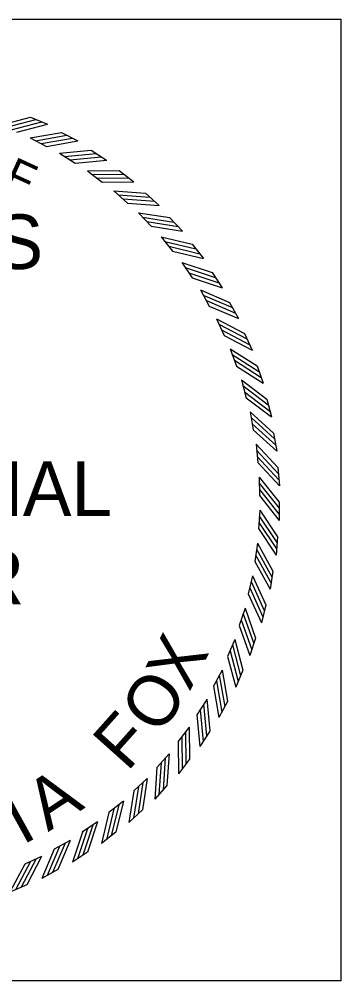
# Model space of a CAD drawing. Extents: x 0 to 1228740, y 0 to 152440.
# Drawn here: x 32.49 to 33.408, y 23.111 to 25.853 of the extents above; entities that cross this region are included whole.
import ezdxf

# ---------------------------------------------------------------- set-up
doc = ezdxf.new("R2010")
doc.units = 0
doc.layers.add('R_No Plot', color=7, linetype='Continuous')
doc.layers.add('STAMP', color=7, linetype='Continuous')

msp = doc.modelspace()

# ---------------------------------------------------------------- linework, layer by layer
at = {"layer": 'R_No Plot'}
msp.add_lwpolyline([(30.6665, 25.8526), (33.4082, 25.8526), (33.4082, 23.1109), (30.6665, 23.1109)], close=True, dxfattribs=at)
at = {"layer": 'STAMP'}
for p, q in [((32.5224, 25.5738), (32.5705, 25.5532)), ((32.6109, 25.53), (32.6572, 25.5055)), ((32.5216, 25.5141), (32.568, 25.4896)), ((32.6052, 25.4706), (32.6494, 25.4423)), ((32.6955, 25.479), (32.7396, 25.4507)), ((32.6849, 25.4203), (32.7266, 25.3884)), ((32.7756, 25.4212), (32.8172, 25.3894)), ((32.7602, 25.3635), (32.7992, 25.3283)), ((32.8506, 25.3569), (32.8895, 25.3218)), ((32.8305, 25.3008), (32.8665, 25.2625)), ((32.9201, 25.2867), (32.956, 25.2485)), ((32.8954, 25.2324), (32.9281, 25.1913)), ((32.9836, 25.211), (33.0161, 25.17)), ((32.9545, 25.1589), (32.9836, 25.1152)), ((33.0406, 25.1304), (33.0696, 25.0868)), ((33.0073, 25.0808), (33.0327, 25.0349)), ((33.0907, 25.0452), (33.1161, 24.9994)), ((33.0534, 24.9986), (33.075, 24.9507)), ((33.1336, 24.9563), (33.1551, 24.9085)), ((33.0927, 24.9129), (33.1102, 24.8634)), ((33.1691, 24.8641), (33.1865, 24.8147)), ((33.1246, 24.8242), (33.138, 24.7734)), ((33.1968, 24.7693), (33.2101, 24.7186)), ((33.1492, 24.7332), (33.1583, 24.6815)), ((33.2165, 24.6725), (33.2256, 24.6209)), ((33.1662, 24.6405), (33.171, 24.5882)), ((33.2283, 24.5744), (33.2331, 24.5222)), ((33.1754, 24.5467), (33.1759, 24.4942)), ((33.2318, 24.4757), (33.2323, 24.4233)), ((33.1769, 24.4524), (33.173, 24.4)), ((33.2273, 24.377), (33.2234, 24.3247)), ((33.1706, 24.3584), (33.1624, 24.3065)), ((33.1565, 24.2651), (33.1441, 24.2141)), ((33.2145, 24.279), (33.2064, 24.2273)), ((33.1938, 24.1825), (33.1814, 24.1316)), ((33.1348, 24.1734), (33.1182, 24.1236)), ((33.1056, 24.0838), (33.0849, 24.0355)), ((33.1651, 24.0879), (33.1485, 24.0382)), ((33.0691, 23.9969), (33.0445, 23.9505)), ((33.1287, 23.9961), (33.1081, 23.9479)), ((33.0255, 23.9133), (32.9972, 23.869)), ((33.0849, 23.9076), (33.0604, 23.8613)), ((32.9752, 23.8336), (32.9433, 23.7918)), ((33.0339, 23.823), (33.0056, 23.7789)), ((32.9184, 23.7583), (32.8832, 23.7193)), ((32.9761, 23.7429), (32.9443, 23.7012)), ((32.8557, 23.6879), (32.8174, 23.652)), ((32.9119, 23.6678), (32.8767, 23.629)), ((32.7873, 23.623), (32.7462, 23.5904)), ((32.8417, 23.5983), (32.8034, 23.5625)), ((32.7138, 23.564), (32.6701, 23.5348)), ((32.766, 23.5349), (32.7249, 23.5023)), ((32.6357, 23.5112), (32.5898, 23.4858)), ((32.6853, 23.4779), (32.6417, 23.4488)), ((32.5535, 23.465), (32.5056, 23.4435)), ((32.6002, 23.4278), (32.5543, 23.4024)), ((32.5112, 23.3848), (32.4634, 23.3634))]:
    msp.add_line(p, q, dxfattribs=at)
for points in [[(32.4346, 25.5506), (32.5223, 25.5738)], [(32.4501, 25.5439), (32.5377, 25.567)], [(32.4669, 25.5371), (32.5546, 25.5602)], [(32.4829, 25.5301), (32.5706, 25.5532)], [(32.5215, 25.5141), (32.6108, 25.53)], [(32.5363, 25.5061), (32.6256, 25.5219)], [(32.5526, 25.4979), (32.6419, 25.5138)], [(32.568, 25.4896), (32.6573, 25.5055)], [(32.6051, 25.4706), (32.6954, 25.479)], [(32.6192, 25.4613), (32.7095, 25.4698)], [(32.6348, 25.4519), (32.7251, 25.4603)], [(32.6494, 25.4423), (32.7397, 25.4507)], [(32.6848, 25.4203), (32.7755, 25.4212)], [(32.6981, 25.4099), (32.7888, 25.4108)], [(32.7128, 25.3992), (32.8035, 25.4001)], [(32.7266, 25.3884), (32.8173, 25.3894)], [(32.7601, 25.3635), (32.8505, 25.357)], [(32.7725, 25.3521), (32.863, 25.3455)], [(32.7863, 25.3402), (32.8767, 25.3336)], [(32.7991, 25.3284), (32.8896, 25.3218)], [(32.8305, 25.3008), (32.92, 25.2868)], [(32.8419, 25.2884), (32.9315, 25.2744)], [(32.8546, 25.2754), (32.9442, 25.2614)], [(32.8664, 25.2625), (32.956, 25.2485)], [(32.8954, 25.2324), (32.9835, 25.2111)], [(32.9057, 25.2191), (32.9939, 25.1978)], [(32.9174, 25.2051), (33.0055, 25.1837)], [(32.9281, 25.1913), (33.0162, 25.17)], [(32.9544, 25.159), (33.0405, 25.1304)], [(32.9637, 25.1448), (33.0497, 25.1163)], [(32.9741, 25.1299), (33.0601, 25.1013)], [(32.9836, 25.1153), (33.0697, 25.0867)], [(33.0072, 25.0809), (33.0906, 25.0453)], [(33.0152, 25.066), (33.0986, 25.0305)], [(33.0244, 25.0503), (33.1078, 25.0147)], [(33.0327, 25.0349), (33.1161, 24.9994)], [(33.0534, 24.9987), (33.1336, 24.9563)], [(33.0601, 24.9832), (33.1403, 24.9409)], [(33.068, 24.9668), (33.1482, 24.9244)], [(33.075, 24.9508), (33.1552, 24.9085)], [(33.0926, 24.9129), (33.169, 24.8641)], [(33.0981, 24.897), (33.1745, 24.8482)], [(33.1045, 24.88), (33.1809, 24.8311)], [(33.1102, 24.8635), (33.1866, 24.8146)], [(33.1246, 24.8243), (33.1967, 24.7693)], [(33.1287, 24.8079), (33.2008, 24.753)], [(33.1337, 24.7904), (33.2059, 24.7355)], [(33.138, 24.7735), (33.2101, 24.7185)], [(33.1492, 24.7333), (33.2165, 24.6725)], [(33.1519, 24.7166), (33.2193, 24.6559)], [(33.1555, 24.6988), (33.2228, 24.638)], [(33.1584, 24.6816), (33.2257, 24.6208)], [(33.1661, 24.6405), (33.2282, 24.5745)], [(33.1675, 24.6237), (33.2296, 24.5577)], [(33.1696, 24.6056), (33.2317, 24.5396)], [(33.171, 24.5882), (33.2331, 24.5222)], [(33.1754, 24.5467), (33.2318, 24.4758)], [(33.1754, 24.5299), (33.2318, 24.4589)], [(33.1759, 24.5117), (33.2324, 24.4407)], [(33.1759, 24.4942), (33.2324, 24.4232)], [(33.1755, 24.4357), (33.2258, 24.3603)], [(33.1768, 24.4525), (33.2272, 24.3771)], [(33.1745, 24.4175), (33.2249, 24.3421)], [(33.1731, 24.4001), (33.2234, 24.3247)], [(33.1705, 24.3584), (33.2145, 24.2791)], [(33.1653, 24.3237), (33.2093, 24.2444)], [(33.1678, 24.3418), (33.2117, 24.2625)], [(33.1625, 24.3065), (33.2064, 24.2272)], [(33.1565, 24.2652), (33.1937, 24.1826)], [(33.1523, 24.2489), (33.1896, 24.1662)], [(33.1441, 24.2142), (33.1814, 24.1315)], [(33.1484, 24.2311), (33.1857, 24.1484)], [(33.1293, 24.1575), (33.1596, 24.0721)], [(33.1348, 24.1735), (33.1651, 24.088)], [(33.1239, 24.1401), (33.1542, 24.0547)], [(33.1183, 24.1236), (33.1486, 24.0382)], [(33.1056, 24.0839), (33.1287, 23.9962)], [(33.092, 24.0515), (33.1151, 23.9639)], [(33.0988, 24.0684), (33.1219, 23.9807)], [(33.085, 24.0355), (33.1081, 23.9479)], [(33.069, 23.997), (33.0849, 23.9077)], [(33.0529, 23.9658), (33.0687, 23.8766)], [(33.061, 23.9821), (33.0769, 23.8928)], [(33.0446, 23.9505), (33.0604, 23.8612)], [(33.0255, 23.9134), (33.0339, 23.8231)], [(33.0068, 23.8837), (33.0152, 23.7934)], [(33.0163, 23.8992), (33.0247, 23.809)], [(32.9972, 23.8691), (33.0056, 23.7788)], [(32.9752, 23.8336), (32.9761, 23.743)], [(32.9541, 23.8056), (32.955, 23.715)], [(32.9648, 23.8203), (32.9657, 23.7297)], [(32.9434, 23.7918), (32.9443, 23.7012)], [(32.907, 23.746), (32.9005, 23.6555)], [(32.9184, 23.7584), (32.9119, 23.6679)], [(32.8833, 23.7193), (32.8767, 23.6289)], [(32.8951, 23.7322), (32.8885, 23.6417)], [(32.8303, 23.6638), (32.8163, 23.5743)], [(32.8433, 23.6766), (32.8293, 23.587)], [(32.8557, 23.688), (32.8417, 23.5984)], [(32.8174, 23.652), (32.8034, 23.5624)], [(32.774, 23.6127), (32.7527, 23.5246)], [(32.7873, 23.6231), (32.766, 23.535)], [(32.7462, 23.5904), (32.7249, 23.5023)], [(32.76, 23.6011), (32.7387, 23.513)], [(32.6998, 23.5548), (32.6712, 23.4688)], [(32.7139, 23.564), (32.6853, 23.478)], [(32.6702, 23.5348), (32.6416, 23.4488)], [(32.6848, 23.5444), (32.6563, 23.4583)], [(32.6209, 23.5032), (32.5854, 23.4198)], [(32.6358, 23.5113), (32.6002, 23.4279)], [(32.5899, 23.4858), (32.5543, 23.4024)], [(32.6052, 23.4941), (32.5696, 23.4107)], [(32.5057, 23.4435), (32.4634, 23.3633)], [(32.5217, 23.4505), (32.4794, 23.3703)], [(32.5381, 23.4583), (32.4958, 23.3781)], [(32.5536, 23.4651), (32.5112, 23.3849)]]:
    msp.add_lwpolyline(points, dxfattribs=at)

# ---------------------------------------------------------------- texts
for s, height, rotation, p in [('F', 0.0953, 335.3628, (32.4384, 25.375)), ('X', 0.1448, 63.5264, (32.976, 23.9326)), ('O', 0.1448, 55.5173, (32.8904, 23.8071)), ('F', 0.1448, 48.2363, (32.7981, 23.7044)), ('A', 0.1448, 33.3104, (32.5723, 23.5345)), ('I', 0.1448, 28.9418, (32.4987, 23.4965))]:
    msp.add_text(s, height=height, rotation=rotation, dxfattribs=at).set_placement(p)
for s, height, p in [('ARKANSAS', 0.15559, (31.4251, 25.1404)), ('PROFESSIONAL', 0.155594, (31.1361, 24.4362)), ('ENGINEER', 0.15559, (31.4177, 24.1843))]:
    msp.add_text(s, height=height, dxfattribs=at).set_placement(p)

doc.saveas('drawing.dxf')
